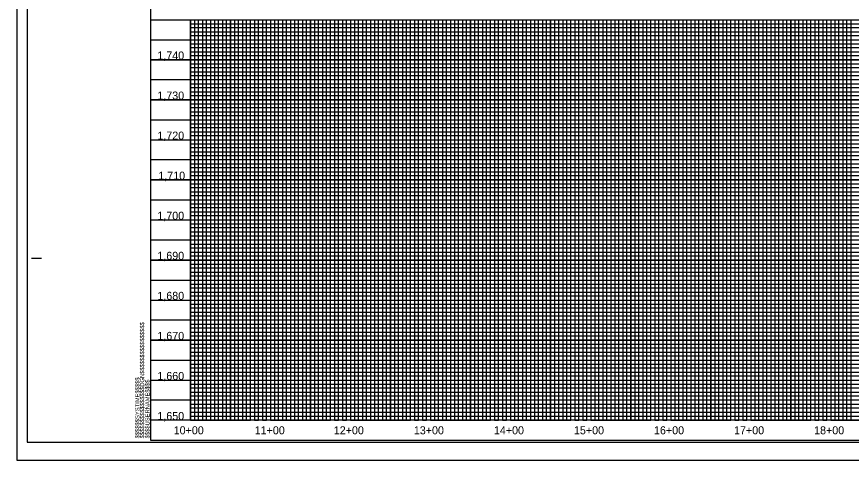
# Model space of a CAD drawing. Extents: x 497599 to 513368, y 404140 to 476034.
# Drawn here: x 505692 to 506734, y 438761 to 439315 of the extents above; entities that cross this region are included whole.
import ezdxf

# ---------------------------------------------------------------- set-up
doc = ezdxf.new("R2010")
doc.units = 0
for name, color, linetype in [('Exist Vertical Profile Vertical Axis Label', 7, 'Continuous'), ('Sheet Cutting Line CELL', 7, 'Continuous'), ('Sheet DOT Grid CELL', 7, 'Continuous'), ('Sheet Layout Profile Border Port 1', 7, 'Continuous'), ('Sheet Layout Profile Border Port 2', 7, 'Continuous'), ('Sheet Plot Border Inside CELL', 7, 'Continuous'), ('Sheet Plot Border Outside CELL', 7, 'Continuous'), ('Sheet Profile CELL', 7, 'Continuous'), ('Sheet Profile Grid Major CELL', 7, 'Continuous'), ('Sheet Profile Grid Middle CELL', 7, 'Continuous'), ('Sheet Profile Grid Minor CELL', 7, 'Continuous')]:
    doc.layers.add(name, color=color, linetype=linetype)

msp = doc.modelspace()

# ---------------------------------------------------------------- linework, layer by layer
at = {"layer": 'Sheet Cutting Line CELL'}
for p, q in [((505691.7, 439861.1), (505691.7, 438761.1)), ((505691.7, 438761.1), (507375.7, 438761.1))]:
    msp.add_line(p, q, dxfattribs=at)
at = {"layer": 'Sheet DOT Grid CELL'}
for p, q in [((505858.7, 439311.1), (507358.6, 439311.1)), ((505908.7, 439311.1), (505908.7, 438811.1)), ((505958.7, 439311.1), (505958.7, 438811.1)), ((506008.7, 439311.1), (506008.7, 438811.1)), ((506058.7, 439311.1), (506058.7, 438811.1)), ((506108.7, 439311.1), (506108.7, 438811.1)), ((506158.7, 439311.1), (506158.7, 438811.1)), ((506208.7, 439311.1), (506208.7, 438811.1)), ((506258.7, 439311.1), (506258.7, 438811.1)), ((506308.7, 439311.1), (506308.7, 438811.1)), ((506358.7, 439311.1), (506358.7, 438811.1)), ((506408.7, 439311.1), (506408.7, 438811.1)), ((506458.7, 439311.1), (506458.7, 438811.1)), ((506508.7, 439311.1), (506508.7, 438811.1)), ((506558.7, 439311.1), (506558.7, 438811.1)), ((506608.7, 439311.1), (506608.7, 438811.1)), ((506658.7, 439311.1), (506658.7, 438811.1)), ((506708.7, 439311.1), (506708.7, 438811.1)), ((505858.7, 439261.1), (507358.6, 439261.1)), ((505858.7, 439211.1), (507358.6, 439211.1)), ((505858.7, 439161.1), (507358.6, 439161.1)), ((505858.7, 439111.1), (507358.6, 439111.1)), ((505858.7, 439061.1), (507358.6, 439061.1)), ((505858.7, 439011.1), (507358.6, 439011.1)), ((505858.7, 438961.1), (507358.6, 438961.1)), ((505858.7, 438911.1), (507358.6, 438911.1)), ((505858.7, 438861.1), (507358.6, 438861.1))]:
    msp.add_line(p, q, dxfattribs=at)
at = {"layer": 'Sheet Layout Profile Border Port 1'}
msp.add_lwpolyline([(505908.7, 439306.1), (507158.7, 439306.1), (507158.6, 439150.1), (507308.7, 439150.1), (507308.7, 438811.1), (505908.7, 438811.1)], close=True, dxfattribs=at)
at = {"layer": 'Sheet Layout Profile Border Port 2'}
msp.add_lwpolyline([(505908.7, 439311.1), (507308.7, 439311.1), (507308.7, 438811.1), (505908.7, 438811.1)], close=True, dxfattribs=at)
at = {"layer": 'Sheet Plot Border Inside CELL'}
msp.add_lwpolyline([(505704.7, 438783.6), (507371.2, 438783.6), (507371.2, 439838.7), (505704.7, 439838.7)], close=True, dxfattribs=at)
at = {"layer": 'Sheet Plot Border Outside CELL'}
msp.add_lwpolyline([(505691.7, 438761.1), (507375.7, 438761.1), (507375.7, 439861.1), (505691.7, 439861.1)], close=True, dxfattribs=at)
at = {"layer": 'Sheet Profile CELL'}
for p, q in [((505858.7, 439311.1), (507358.7, 439311.1)), ((505710.2, 439013.6), (505722.7, 439013.6)), ((507358.7, 438811.1), (505858.7, 438811.1)), ((505858.7, 438786.1), (507358.7, 438786.1)), ((505858.7, 438786.1), (505858.7, 438786.1)), ((505858.7, 438786.1), (505858.7, 438786.1)), ((505858.7, 438786.1), (505858.7, 438786.1)), ((505858.7, 438786.1), (505858.7, 438786.1)), ((505858.7, 438786.1), (505858.7, 438786.1)), ((505858.7, 438786.1), (505858.7, 438786.1)), ((505858.7, 438786.1), (505858.7, 438786.1))]:
    msp.add_line(p, q, dxfattribs=at)
msp.add_lwpolyline([(507358.7, 439836.1), (505858.7, 439836.1), (505858.7, 438786.1), (507358.7, 438786.1)], close=True, dxfattribs=at)
msp.add_lwpolyline([(505896.2, 438786.1), (505896.2, 438786.1)], dxfattribs=at)
at = {"layer": 'Sheet Profile Grid Major CELL'}
for p, q in [((506558.7, 439311.1), (506608.7, 439311.1)), ((506558.7, 439311.1), (506608.7, 439311.1)), ((506658.7, 439311.1), (506708.7, 439311.1)), ((506658.7, 439311.1), (506708.7, 439311.1)), ((505858.7, 438761.1), (505858.7, 438761.1))]:
    msp.add_line(p, q, dxfattribs=at)
for points in [[(505908.7, 439311.1), (505908.7, 438811.1), (505958.7, 438811.1), (505958.7, 439311.1), (506008.7, 439311.1), (506008.7, 438811.1), (506058.7, 438811.1), (506058.7, 439311.1), (506108.7, 439311.1), (506108.7, 438811.1), (506158.7, 438811.1), (506158.7, 439311.1), (506208.7, 439311.1), (506208.7, 438811.1), (506258.7, 438811.1), (506258.7, 439311.1), (506308.7, 439311.1), (506308.7, 438811.1), (506358.7, 438811.1), (506358.7, 439311.1), (506408.7, 439311.1), (506408.7, 438811.1), (506458.7, 438811.1), (506458.7, 439311.1), (506508.7, 439311.1), (506508.7, 438811.1), (506558.7, 438811.1), (506558.7, 439311.1), (506608.7, 439311.1), (506608.7, 438811.1), (506658.7, 438811.1), (506658.7, 439311.1), (506708.7, 439311.1), (506708.7, 438811.1), (506758.7, 438811.1)], [(507358.7, 439261.1), (505858.7, 439261.1)], [(507358.7, 439211.1), (505858.7, 439211.1), (505858.7, 439161.1), (507358.7, 439161.1)], [(507358.7, 439111.1), (505858.7, 439111.1), (505858.7, 439061.1), (507358.7, 439061.1)], [(507358.7, 439011.1), (505858.7, 439011.1), (505858.7, 438961.1), (507358.7, 438961.1)], [(507358.7, 438911.1), (505858.7, 438911.1), (505858.7, 438911.1), (505858.7, 438861.1), (507358.7, 438861.1)], [(507358.7, 438811.1), (505858.7, 438811.1)]]:
    msp.add_lwpolyline(points, dxfattribs=at)
at = {"layer": 'Sheet Profile Grid Middle CELL'}
for points in [[(505883.7, 439311.1), (505933.7, 439311.1), (505933.7, 438811.1), (505983.7, 438811.1), (505983.7, 439311.1), (506033.7, 439311.1), (506033.7, 438811.1), (506083.7, 438811.1), (506083.7, 439311.1), (506133.7, 439311.1), (506133.7, 438811.1), (506183.7, 438811.1), (506183.7, 439311.1), (506233.7, 439311.1), (506233.7, 438811.1), (506283.7, 438811.1), (506283.7, 439311.1), (506333.7, 439311.1), (506333.7, 438811.1), (506383.7, 438811.1), (506383.7, 439311.1), (506433.7, 439311.1), (506433.7, 438811.1), (506483.7, 438811.1), (506483.7, 438811.1), (506483.7, 439311.1), (506533.7, 439311.1), (506533.7, 438811.1), (506583.7, 438811.1), (506583.7, 439311.1), (506633.7, 439311.1), (506633.7, 438811.1), (506683.7, 438811.1), (506683.7, 439311.1), (506733.7, 439311.1), (506733.7, 438811.1), (506783.7, 438811.1)], [(505858.7, 439286.1), (507358.7, 439286.1)], [(507358.7, 439236.1), (505858.7, 439236.1), (505858.7, 439186.1), (507358.7, 439186.1)], [(507358.7, 439136.1), (505858.7, 439136.1), (505858.7, 439086.1), (507358.7, 439086.1)], [(507358.7, 439036.1), (505858.7, 439036.1), (505858.7, 438986.1), (507358.7, 438986.1)], [(507358.7, 438936.1), (505858.7, 438936.1), (505858.7, 438886.1), (507358.7, 438886.1)], [(507358.7, 438836.1), (505858.7, 438836.1)]]:
    msp.add_lwpolyline(points, dxfattribs=at)
at = {"layer": 'Sheet Profile Grid Minor CELL'}
for p, q in [((505908.7, 439306.1), (507308.7, 439306.1)), ((507308.7, 439301.1), (505908.7, 439301.1)), ((505908.7, 439296.1), (507308.7, 439296.1)), ((507308.7, 439291.1), (505908.7, 439291.1)), ((505908.7, 439281.1), (507308.7, 439281.1)), ((507308.7, 439276.1), (505908.7, 439276.1)), ((505908.7, 439271.1), (507308.7, 439271.1)), ((507308.7, 439266.1), (505908.7, 439266.1)), ((505908.7, 439256.1), (507308.7, 439256.1)), ((507308.7, 439251.1), (505908.7, 439251.1)), ((505908.7, 439246.1), (507308.7, 439246.1)), ((507308.7, 439241.1), (505908.7, 439241.1)), ((505908.7, 439231.1), (507308.7, 439231.1)), ((507308.7, 439226.1), (505908.7, 439226.1)), ((505908.7, 439221.1), (507308.7, 439221.1)), ((507308.7, 439216.1), (505908.7, 439216.1)), ((505908.7, 439206.1), (507308.7, 439206.1)), ((507308.7, 439201.1), (505908.7, 439201.1)), ((505908.7, 439196.1), (507308.7, 439196.1)), ((507308.7, 439191.1), (505908.7, 439191.1)), ((505908.7, 439181.1), (507308.7, 439181.1)), ((507308.7, 439176.1), (505908.7, 439176.1)), ((505908.7, 439171.1), (507308.7, 439171.1)), ((507308.7, 439166.1), (505908.7, 439166.1)), ((505908.7, 439156.1), (507308.7, 439156.1)), ((507308.7, 439151.1), (505908.7, 439151.1)), ((505908.7, 439146.1), (507308.7, 439146.1)), ((507308.7, 439141.1), (505908.7, 439141.1)), ((505908.7, 439131.1), (507308.7, 439131.1)), ((507308.7, 439126.1), (505908.7, 439126.1)), ((505908.7, 439121.1), (507308.7, 439121.1)), ((507308.7, 439116.1), (505908.7, 439116.3)), ((505908.7, 439106.1), (507308.7, 439106.1)), ((507308.7, 439101.1), (505908.7, 439101.1)), ((505908.7, 439096.1), (507308.7, 439096.1)), ((507308.7, 439091.1), (505908.7, 439091.1)), ((505908.7, 439081.1), (507308.7, 439081.1)), ((507308.7, 439076.1), (505908.7, 439076.1)), ((505908.7, 439071.1), (507308.7, 439071.1)), ((507308.7, 439066.1), (505908.7, 439066.1)), ((505908.7, 439056.1), (507308.7, 439056.1)), ((507308.7, 439051.1), (505908.7, 439051.1)), ((505908.7, 439046.1), (507308.7, 439046.1)), ((507308.7, 439041.1), (505908.7, 439041.1)), ((505908.7, 439031.1), (507308.7, 439031.1)), ((507308.7, 439026.1), (505908.7, 439026.1)), ((505908.7, 439021.1), (507308.7, 439021.1)), ((507308.7, 439016.1), (505908.7, 439016.1)), ((505908.7, 439006.1), (507308.7, 439006.1)), ((507308.7, 439001.1), (505908.7, 439001.1)), ((505908.7, 438996.1), (507308.7, 438996.1)), ((507308.7, 438991.1), (505908.7, 438991.1)), ((505908.7, 438981.1), (507308.7, 438981.1)), ((507308.7, 438976.1), (505908.7, 438976.1)), ((505908.7, 438971.1), (507308.7, 438971.1)), ((507308.7, 438966.1), (505908.7, 438966.1)), ((505908.7, 438956.1), (507308.7, 438956.1)), ((507308.7, 438951.1), (505908.7, 438951.1)), ((505908.7, 438946.1), (507308.7, 438946.1)), ((507308.7, 438941.1), (505908.7, 438941.1)), ((505908.7, 438931.1), (507308.7, 438931.1)), ((507308.7, 438926.1), (505908.7, 438926.1)), ((505908.7, 438921.1), (507308.7, 438921.1)), ((507308.7, 438916.1), (505908.7, 438916.1)), ((505908.7, 438906.1), (507308.7, 438906.1)), ((507308.7, 438901.1), (505908.7, 438901.1)), ((505908.7, 438896.1), (507308.7, 438896.1)), ((507308.7, 438891.1), (505908.7, 438891.1)), ((505908.7, 438881.1), (507308.7, 438881.1)), ((507308.7, 438876.1), (505908.7, 438876.1)), ((505908.7, 438871.1), (507308.7, 438871.1)), ((507308.7, 438866.1), (505908.7, 438866.1)), ((505908.7, 438856.1), (507308.7, 438856.1)), ((507308.7, 438851.1), (505908.7, 438851.1)), ((505908.7, 438846.1), (507308.7, 438846.1)), ((507308.7, 438841.1), (505908.7, 438841.1)), ((505908.7, 438831.1), (507308.7, 438831.1)), ((507308.7, 438826.1), (505908.7, 438826.1)), ((505908.7, 438821.1), (507308.7, 438821.1)), ((505908.7, 438816.1), (507308.7, 438816.1))]:
    msp.add_line(p, q, dxfattribs=at)
for points in [[(505908.7, 439311.1), (505913.7, 439311.1), (505913.7, 438811.1), (505918.7, 438811.1), (505918.7, 439311.1), (505923.7, 439311.1), (505923.7, 438811.1), (505928.7, 438811.1), (505928.7, 439311.1), (505938.7, 439311.1), (505938.7, 438811.1), (505943.7, 438811.1), (505943.7, 439311.1), (505948.7, 439311.1), (505948.7, 438811.1), (505953.7, 438811.1), (505963.7, 438811.1), (505968.7, 438811.1), (505968.7, 439311.1), (505973.7, 439311.1), (505973.7, 438811.1), (505978.7, 438811.1), (505978.7, 439311.1), (505988.7, 439311.1), (505988.7, 438811.1), (505993.7, 438811.1), (505993.7, 439311.1), (505998.7, 439311.1), (505998.7, 438811.1), (506003.7, 438811.1), (506003.7, 439311.1), (506013.7, 439311.1), (506013.7, 438811.1), (506018.7, 438811.1), (506018.7, 439311.1), (506023.7, 439311.1), (506023.7, 438811.1), (506028.7, 438811.1), (506028.7, 439311.1), (506038.7, 439311.1), (506038.7, 438811.1), (506043.7, 438811.1), (506043.7, 439311.1), (506048.7, 439311.1), (506048.7, 438811.1), (506053.7, 438811.1), (506053.7, 439311.1), (506063.7, 439311.1), (506063.7, 438811.1), (506068.7, 438811.1), (506068.7, 439311.1), (506073.7, 439311.1), (506073.7, 438811.1), (506078.7, 438811.1), (506078.7, 439311.1), (506088.7, 439311.1), (506088.7, 438811.1), (506093.7, 438811.1), (506093.7, 439311.1), (506098.7, 439311.1), (506098.7, 438811.1), (506103.7, 438811.1), (506103.7, 439311.1), (506113.7, 439311.1), (506113.7, 438811.1), (506118.7, 438811.1), (506118.7, 439311.1), (506123.7, 439311.1), (506123.7, 438811.1)], [(505953.7, 438811.1), (505953.7, 439311.1), (505963.7, 439311.1), (505963.7, 438811.1)], [(506123.7, 438811.1), (506128.7, 438811.1), (506128.7, 439311.1), (506138.7, 439311.1), (506138.7, 438811.1), (506143.7, 438811.1), (506143.7, 439311.1), (506148.7, 439311.1), (506148.7, 438811.1), (506153.7, 438811.1), (506153.7, 439311.1), (506163.7, 439311.1), (506163.7, 438811.1), (506168.7, 438811.1), (506168.7, 439311.1), (506173.7, 439311.1), (506173.7, 438811.1), (506178.7, 438811.1), (506178.7, 439311.1), (506188.7, 439311.1), (506188.7, 438811.1), (506193.7, 438811.1), (506193.7, 439311.1), (506198.7, 439311.1), (506198.7, 438811.1), (506203.7, 438811.1), (506203.7, 439311.1), (506213.7, 439311.1), (506213.7, 438811.1), (506218.7, 438811.1), (506218.7, 439311.1), (506223.7, 439311.1), (506223.7, 438811.1), (506228.7, 438811.1), (506228.7, 439311.1), (506238.7, 439311.1), (506238.7, 438811.1), (506243.7, 438811.1), (506243.7, 439311.1), (506248.7, 439311.1), (506248.7, 438811.1), (506253.7, 438811.1), (506253.7, 439311.1), (506263.7, 439311.1), (506263.7, 438811.1), (506268.7, 438811.1), (506268.7, 439311.1), (506273.7, 439311.1), (506273.7, 438811.1), (506278.7, 438811.1), (506278.7, 439311.1), (506288.7, 439311.1), (506288.7, 438811.1), (506293.7, 438811.1), (506293.7, 439311.1), (506298.7, 439311.1), (506298.7, 438811.1), (506303.7, 438811.1), (506303.7, 439311.1), (506313.7, 439311.1), (506313.7, 438811.1), (506318.7, 438811.1), (506318.7, 439311.1), (506323.7, 439311.1), (506323.7, 438811.1), (506328.7, 438811.1), (506328.7, 439311.1), (506338.7, 439311.1), (506338.7, 438811.1), (506343.7, 438811.1), (506343.7, 439311.1), (506348.7, 439311.1), (506348.7, 438811.1), (506353.7, 438811.1), (506353.7, 439311.1), (506363.7, 439311.1), (506363.7, 438811.1), (506368.7, 438811.1), (506368.7, 439311.1), (506373.7, 439311.1), (506373.7, 438811.1), (506378.7, 438811.1), (506378.7, 439311.1), (506388.7, 439311.1), (506388.7, 438811.1), (506393.7, 438811.1), (506393.7, 439311.1), (506398.7, 439311.1), (506398.7, 438811.1), (506403.7, 438811.1), (506403.7, 439311.1), (506413.7, 439311.1), (506413.7, 438811.1), (506418.7, 438811.1), (506418.7, 439311.1), (506423.7, 439311.1), (506423.7, 438811.1), (506428.7, 438811.1), (506428.7, 439311.1), (506438.7, 439311.1)], [(506438.7, 439311.1), (506438.7, 438811.1), (506443.7, 438811.1), (506443.7, 439311.1), (506448.7, 439311.1), (506448.7, 438811.1), (506453.7, 438811.1), (506453.7, 439311.1), (506463.7, 439311.1), (506463.7, 438811.1), (506468.7, 438811.1), (506468.7, 439311.1), (506473.7, 439311.1), (506473.7, 438811.1), (506478.7, 438811.1), (506478.7, 439311.1), (506488.7, 439311.1), (506488.7, 438811.1), (506493.7, 438811.1), (506493.7, 439311.1), (506498.7, 439311.1), (506498.7, 438811.1), (506503.7, 438811.1), (506503.7, 439311.1), (506513.7, 439311.1), (506513.7, 438811.1), (506518.7, 438811.1), (506518.7, 439311.1), (506523.7, 439311.1), (506523.7, 438811.1), (506528.7, 438811.1), (506528.7, 439311.1), (506538.7, 439311.1), (506538.7, 438811.1), (506543.7, 438811.1), (506543.7, 439311.1), (506548.7, 439311.1), (506548.7, 438811.1), (506553.7, 438811.1), (506553.7, 439311.1), (506563.7, 439311.1), (506563.7, 438811.1), (506563.7, 438811.1), (506568.7, 438811.1), (506568.7, 439311.1), (506573.7, 439311.1), (506573.7, 438811.1), (506578.7, 438811.1), (506578.7, 439311.1), (506588.7, 439311.1), (506588.7, 438811.1), (506593.7, 438811.1), (506593.7, 439311.1), (506598.7, 439311.1), (506598.7, 438811.1), (506603.7, 438811.1), (506603.7, 439311.1), (506613.7, 439311.1), (506613.7, 438811.1), (506618.7, 438811.1), (506618.7, 439311.1), (506623.7, 439311.1), (506623.7, 438811.1), (506628.7, 438811.1), (506628.7, 439311.1), (506638.7, 439311.1), (506638.7, 438811.1), (506643.7, 438811.1), (506643.7, 439311.1), (506648.7, 439311.1), (506648.7, 438811.1), (506653.7, 438811.1), (506653.7, 439311.1), (506663.7, 439311.1), (506663.7, 438811.1), (506668.7, 438811.1), (506668.7, 439311.1), (506673.7, 439311.1), (506673.7, 438811.1), (506678.7, 438811.1), (506678.7, 439311.1), (506688.7, 439311.1), (506688.7, 438811.1), (506693.7, 438811.1), (506693.7, 439311.1), (506698.7, 439311.1), (506698.7, 438811.1), (506703.7, 438811.1), (506703.7, 439311.1), (506713.7, 439311.1), (506713.7, 438811.1), (506718.4, 438811.7), (506718.7, 438811.1), (506718.7, 439311.1), (506723.7, 439311.1), (506723.7, 438811.1), (506728.7, 438811.1), (506728.7, 439311.1), (506738.7, 439311.1)]]:
    msp.add_lwpolyline(points, dxfattribs=at)

# ---------------------------------------------------------------- texts
at = {"layer": 'Exist Vertical Profile Vertical Axis Label'}
for s, p in [('1,740', (505867.4, 439261.4)), ('1,730', (505867.4, 439211.4)), ('1,720', (505867.4, 439161.4)), ('1,710', (505868.6, 439111.4)), ('1,700', (505867.4, 439061.4)), ('1,690', (505867.4, 439011.4)), ('1,680', (505867.4, 438961.4)), ('1,670', (505867.4, 438911.4)), ('1,660', (505867.4, 438861.4)), ('1,650', (505867.4, 438811.4)), ('10+00', (505887.8, 438793.6)), ('11+00', (505989, 438793.6)), ('12+00', (506087.8, 438793.6)), ('13+00', (506187.8, 438793.6)), ('14+00', (506287.8, 438793.6)), ('15+00', (506387.8, 438793.6)), ('16+00', (506487.8, 438793.6)), ('17+00', (506587.8, 438793.6)), ('18+00', (506687.8, 438793.6))]:
    msp.add_text(s, height=10, dxfattribs=at).set_placement(p)
at = {"layer": 'Sheet Profile CELL'}
for s, p in [('$$$$$$$$$$$$$$$$DGN$$$$$$$$$$$$$$$$', (505851, 438788.5)), ('$$$$$$SYSTIME$$$$$', (505845, 438788.5)), ('$$$$USERNAME$$$$', (505857.6, 438788.5))]:
    msp.add_text(s, height=5.25, rotation=90, dxfattribs=at).set_placement(p)

doc.saveas('drawing.dxf')
